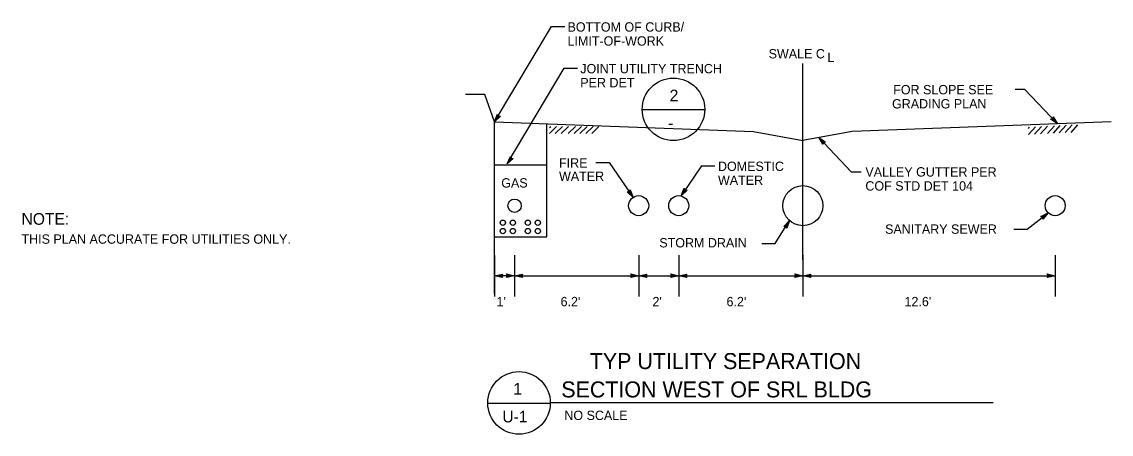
# Model space of a CAD drawing. Extents: x -1680 to 1155, y -802 to 799.
# Drawn here: x -1680 to -864, y 490 to 799 of the extents above; entities that cross this region are included whole.
import ezdxf

# ---------------------------------------------------------------- set-up
doc = ezdxf.new("R2010")
doc.units = 0
for name, color, linetype in [('New Utility (40)', 7, 'Continuous'), ('Nongeo Data(60)', 7, 'Continuous'), ('Sheet Format(10)', 7, 'Continuous')]:
    doc.layers.add(name, color=color, linetype=linetype)

msp = doc.modelspace()

# ---------------------------------------------------------------- linework, layer by layer
at = {"layer": 'Nongeo Data(60)'}
for p, q in [((-1325.56, 723.99), (-1282.86, 795.41)), ((-1282.86, 795.41), (-1272.86, 795.41)), ((-1094.56, 620.62), (-1094.56, 767.64)), ((-1315.99, 692.36), (-1273.29, 764.2)), ((-1273.29, 764.2), (-1263.29, 764.2)), ((-1332.86, 744.3), (-1347.41, 744.3)), ((-1325.56, 723.99), (-1332.86, 744.3)), ((-928.19, 748.17), (-935.6, 748.17)), ((-903.83, 722.45), (-928.19, 748.17)), ((-1325.56, 723.99), (-1323.24, 729.68)), ((-1321.05, 728.17), (-1325.56, 723.99)), ((-1324.77, 725.14), (-1323.08, 729.29)), ((-1321.46, 728.19), (-1324.77, 725.13)), ((-1323.99, 726.26), (-1322.9, 728.94)), ((-1321.89, 728.2), (-1323.99, 726.26)), ((-1323.24, 729.68), (-1323.24, 729.68)), ((-1323.24, 729.68), (-1322.6, 728.27)), ((-1323.2, 727.4), (-1322.73, 728.55)), ((-1322.28, 728.26), (-1323.2, 727.4)), ((-1322.6, 728.27), (-1321.05, 728.17)), ((-1321.05, 728.17), (-1321.05, 728.17)), ((-1215.19, 733.21), (-1168.07, 733.21)), ((-907.41, 726.22), (-906.99, 727.73)), ((-907.33, 726.54), (-906.68, 725.46)), ((-907.19, 726.91), (-905.73, 724.46)), ((-907.09, 727.32), (-904.78, 723.45)), ((-906.99, 727.73), (-906.99, 727.73)), ((-906.99, 727.73), (-903.83, 722.45)), ((-1325.56, 723.99), (-1131.48, 716.55)), ((-1325.56, 723.99), (-1325.56, 723.99)), ((-1325.56, 595.29), (-1325.56, 723.99)), ((-1286.35, 637.8), (-1286.35, 722.49)), ((-1284.49, 715.06), (-1279.02, 720.53)), ((-1284.41, 719.56), (-1283.44, 720.53)), ((-1280.07, 715.06), (-1274.6, 720.53)), ((-1275.65, 715.06), (-1270.18, 720.53)), ((-1270.37, 715.06), (-1264.9, 720.53)), ((-1265.95, 715.06), (-1260.48, 720.53)), ((-1261.53, 715.06), (-1256.06, 720.53)), ((-1257.11, 715.06), (-1251.64, 720.53)), ((-1252.69, 715.06), (-1247.39, 720.36)), ((-863.56, 723.99), (-1057.64, 716.55)), ((-925.57, 718.97), (-924.65, 719.99)), ((-925.43, 714.47), (-920.23, 720.2)), ((-921.01, 714.69), (-915.82, 720.42)), ((-916.6, 714.91), (-911.41, 720.64)), ((-911.32, 715.16), (-906.13, 720.89)), ((-908.92, 725.89), (-907.41, 726.22)), ((-903.83, 722.45), (-908.92, 725.89)), ((-908.92, 725.89), (-908.92, 725.89)), ((-904.79, 723.46), (-908.5, 725.97)), ((-905.73, 724.46), (-908.13, 726.08)), ((-906.68, 725.46), (-907.71, 726.15)), ((-906.91, 715.38), (-901.71, 721.11)), ((-903.83, 722.45), (-903.83, 722.45)), ((-902.49, 715.6), (-897.3, 721.33)), ((-898.08, 715.81), (-892.89, 721.54)), ((-893.67, 716.03), (-888.63, 721.59)), ((-1131.48, 716.55), (-1094.56, 709.98)), ((-1057.64, 716.55), (-1094.56, 709.98)), ((-1082.66, 712.1), (-1058.31, 686.38)), ((-1079.51, 706.82), (-1082.66, 712.1)), ((-1082.66, 712.1), (-1082.66, 712.1)), ((-1082.66, 712.1), (-1077.57, 708.65)), ((-1079.4, 707.22), (-1081.72, 711.09)), ((-1081.71, 711.09), (-1078, 708.58)), ((-1079.3, 707.64), (-1080.77, 710.09)), ((-1080.77, 710.09), (-1078.37, 708.47)), ((-1079.17, 708), (-1079.82, 709.08)), ((-1079.82, 709.08), (-1078.79, 708.39)), ((-1079.09, 708.32), (-1079.51, 706.82)), ((-1079.51, 706.82), (-1079.51, 706.82)), ((-1077.57, 708.65), (-1079.09, 708.32)), ((-1077.57, 708.65), (-1077.57, 708.65)), ((-1315.99, 692.36), (-1313.67, 698.06)), ((-1311.48, 696.54), (-1315.99, 692.36)), ((-1315.2, 693.51), (-1313.51, 697.66)), ((-1311.89, 696.56), (-1315.2, 693.5)), ((-1314.42, 694.63), (-1313.33, 697.31)), ((-1312.32, 696.57), (-1314.42, 694.63)), ((-1313.67, 698.06), (-1313.67, 698.06)), ((-1313.67, 698.06), (-1313.03, 696.64)), ((-1313.63, 695.77), (-1313.16, 696.92)), ((-1312.71, 696.63), (-1313.63, 695.77)), ((-1313.03, 696.64), (-1311.48, 696.54)), ((-1311.48, 696.54), (-1311.48, 696.54)), ((-1286.35, 691.49), (-1325.56, 691.49)), ((-1315.99, 692.36), (-1315.99, 692.36)), ((-1249.65, 693.39), (-1239.65, 693.39)), ((-1239.65, 693.39), (-1221.77, 667.31)), ((-1170.61, 690.87), (-1185.78, 668.39)), ((-1170.61, 690.87), (-1160.61, 690.87)), ((-1058.31, 686.38), (-1050.9, 686.38)), ((-1226.26, 671.5), (-1224.71, 671.6)), ((-1221.77, 667.31), (-1226.26, 671.5)), ((-1226.26, 671.5), (-1226.26, 671.5)), ((-1222.56, 668.45), (-1225.83, 671.51)), ((-1223.33, 669.59), (-1225.45, 671.56)), ((-1224.11, 670.73), (-1225.02, 671.57)), ((-1224.71, 671.6), (-1224.06, 673.01)), ((-1224.58, 671.9), (-1224.11, 670.73)), ((-1224.39, 672.24), (-1223.33, 669.59)), ((-1224.23, 672.63), (-1222.55, 668.44)), ((-1224.06, 673.01), (-1224.06, 673.01)), ((-1224.06, 673.01), (-1221.77, 667.31)), ((-1185.78, 668.39), (-1183.52, 674.1)), ((-1181.31, 672.61), (-1185.78, 668.39)), ((-1185, 669.54), (-1183.36, 673.71)), ((-1181.72, 672.63), (-1185, 669.53)), ((-1184.23, 670.68), (-1183.17, 673.37)), ((-1182.15, 672.64), (-1184.23, 670.68)), ((-1183.52, 674.1), (-1183.52, 674.1)), ((-1183.52, 674.1), (-1182.87, 672.7)), ((-1183.45, 671.82), (-1183, 672.97)), ((-1182.54, 672.69), (-1183.45, 671.82)), ((-1182.87, 672.7), (-1181.31, 672.61)), ((-1181.31, 672.61), (-1181.31, 672.61)), ((-1221.77, 667.31), (-1221.77, 667.31)), ((-1185.78, 668.39), (-1185.78, 668.39)), ((-926.54, 643.41), (-910.83, 655.76)), ((-916.37, 653.11), (-910.83, 655.76)), ((-914.92, 652.55), (-916.37, 653.11)), ((-916.37, 653.11), (-916.37, 653.11)), ((-915.98, 652.97), (-911.91, 654.91)), ((-915.58, 652.83), (-913, 654.06)), ((-915.22, 652.66), (-914.09, 653.21)), ((-914.09, 653.21), (-914.87, 652.25)), ((-913, 654.06), (-914.83, 651.82)), ((-911.92, 654.9), (-914.76, 651.44)), ((-910.83, 655.76), (-914.72, 651.01)), ((-910.83, 655.76), (-910.83, 655.76)), ((-1115.35, 632.79), (-1104.62, 649.98)), ((-1108.93, 645.6), (-1104.62, 649.98)), ((-1107.37, 645.57), (-1108.93, 645.6)), ((-1108.93, 645.6), (-1108.93, 645.6)), ((-1108.52, 645.59), (-1105.35, 648.81)), ((-1108.09, 645.6), (-1106.08, 647.63)), ((-1107.7, 645.57), (-1106.82, 646.46)), ((-1106.67, 644.18), (-1107.37, 645.57)), ((-1106.82, 646.46), (-1107.23, 645.3)), ((-1106.08, 647.63), (-1107.05, 644.91)), ((-1105.35, 648.79), (-1106.85, 644.57)), ((-1104.62, 649.98), (-1106.67, 644.18)), ((-1104.62, 649.98), (-1104.62, 649.98)), ((-914.72, 651.01), (-914.92, 652.55)), ((-914.72, 651.01), (-914.72, 651.01)), ((-1325.56, 637.8), (-1286.35, 637.8)), ((-1106.67, 644.18), (-1106.67, 644.18)), ((-936.54, 643.41), (-926.54, 643.41)), ((-1125.35, 632.79), (-1115.35, 632.79)), ((-1325.56, 624.01), (-1325.56, 593.15)), ((-1310.56, 624.01), (-1310.56, 593.15)), ((-1217.56, 624.01), (-1217.56, 593.15)), ((-1187.56, 624.01), (-1187.56, 593.15)), ((-1094.56, 624.01), (-1094.56, 593.15)), ((-905.56, 624.01), (-905.56, 593.15)), ((-1325.56, 608.58), (-1319.56, 609.91)), ((-1310.56, 608.58), (-1325.56, 608.58)), ((-1319.56, 607.24), (-1325.56, 608.58)), ((-1325.56, 608.58), (-1325.56, 608.58)), ((-1319.77, 607.6), (-1324.18, 608.58)), ((-1324.17, 608.58), (-1319.79, 609.55)), ((-1322.79, 608.58), (-1319.97, 609.2)), ((-1320.01, 607.96), (-1322.79, 608.58)), ((-1321.41, 608.58), (-1320.2, 608.85)), ((-1320.18, 608.3), (-1321.41, 608.58)), ((-1319.56, 609.91), (-1320.36, 608.58)), ((-1320.36, 608.58), (-1319.56, 607.24)), ((-1319.56, 609.91), (-1319.56, 609.91)), ((-1319.56, 607.24), (-1319.56, 607.24)), ((-1315.76, 608.58), (-1316.56, 609.92)), ((-1316.56, 609.92), (-1316.56, 609.92)), ((-1316.56, 609.92), (-1310.56, 608.58)), ((-1310.56, 608.58), (-1316.56, 607.25)), ((-1316.56, 607.25), (-1315.76, 608.58)), ((-1316.56, 607.25), (-1316.56, 607.25)), ((-1316.34, 609.56), (-1311.94, 608.58)), ((-1311.95, 608.58), (-1316.32, 607.61)), ((-1313.32, 608.58), (-1316.15, 607.96)), ((-1316.11, 609.2), (-1313.32, 608.58)), ((-1315.93, 608.86), (-1314.7, 608.58)), ((-1314.7, 608.58), (-1315.91, 608.32)), ((-1310.56, 608.58), (-1304.56, 609.91)), ((-1310.56, 608.58), (-1217.56, 608.58)), ((-1310.56, 608.58), (-1310.56, 608.58)), ((-1304.56, 607.24), (-1310.56, 608.58)), ((-1310.56, 608.58), (-1310.56, 608.58)), ((-1304.77, 607.6), (-1309.18, 608.58)), ((-1309.17, 608.58), (-1304.79, 609.55)), ((-1307.79, 608.58), (-1304.97, 609.2)), ((-1305.01, 607.96), (-1307.79, 608.58)), ((-1306.41, 608.58), (-1305.2, 608.85)), ((-1305.18, 608.3), (-1306.41, 608.58)), ((-1304.56, 609.91), (-1305.36, 608.58)), ((-1305.36, 608.58), (-1304.56, 607.24)), ((-1304.56, 609.91), (-1304.56, 609.91)), ((-1304.56, 607.24), (-1304.56, 607.24)), ((-1222.76, 608.58), (-1223.56, 609.92)), ((-1223.56, 609.92), (-1223.56, 609.92)), ((-1223.56, 609.92), (-1217.56, 608.58)), ((-1217.56, 608.58), (-1223.56, 607.25)), ((-1223.56, 607.25), (-1222.76, 608.58)), ((-1223.56, 607.25), (-1223.56, 607.25)), ((-1223.34, 609.56), (-1218.94, 608.58)), ((-1218.95, 608.58), (-1223.32, 607.61)), ((-1220.32, 608.58), (-1223.15, 607.96)), ((-1223.11, 609.2), (-1220.32, 608.58)), ((-1222.93, 608.86), (-1221.7, 608.58)), ((-1221.7, 608.58), (-1222.91, 608.32)), ((-1217.56, 608.58), (-1211.56, 609.91)), ((-1217.56, 608.58), (-1187.56, 608.58)), ((-1217.56, 608.58), (-1217.56, 608.58)), ((-1211.56, 607.24), (-1217.56, 608.58)), ((-1217.56, 608.58), (-1217.56, 608.58)), ((-1211.77, 607.6), (-1216.18, 608.58)), ((-1216.17, 608.58), (-1211.79, 609.55)), ((-1214.79, 608.58), (-1211.97, 609.2)), ((-1212.01, 607.96), (-1214.79, 608.58)), ((-1213.41, 608.58), (-1212.2, 608.85)), ((-1212.18, 608.3), (-1213.41, 608.58)), ((-1211.56, 609.91), (-1212.36, 608.58)), ((-1212.36, 608.58), (-1211.56, 607.24)), ((-1211.56, 609.91), (-1211.56, 609.91)), ((-1211.56, 607.24), (-1211.56, 607.24)), ((-1192.76, 608.58), (-1193.56, 609.92)), ((-1193.56, 609.92), (-1193.56, 609.92)), ((-1193.56, 609.92), (-1187.56, 608.58)), ((-1187.56, 608.58), (-1193.56, 607.25)), ((-1193.56, 607.25), (-1192.76, 608.58)), ((-1193.56, 607.25), (-1193.56, 607.25)), ((-1193.34, 609.56), (-1188.94, 608.58)), ((-1188.95, 608.58), (-1193.32, 607.61)), ((-1190.32, 608.58), (-1193.15, 607.96)), ((-1193.11, 609.2), (-1190.32, 608.58)), ((-1192.93, 608.86), (-1191.7, 608.58)), ((-1191.7, 608.58), (-1192.91, 608.32)), ((-1187.56, 608.58), (-1181.56, 609.91)), ((-1187.56, 608.58), (-1094.56, 608.58)), ((-1187.56, 608.58), (-1187.56, 608.58)), ((-1181.56, 607.24), (-1187.56, 608.58)), ((-1187.56, 608.58), (-1187.56, 608.58)), ((-1181.77, 607.6), (-1186.18, 608.58)), ((-1186.17, 608.58), (-1181.79, 609.55)), ((-1184.79, 608.58), (-1181.97, 609.2)), ((-1182.01, 607.96), (-1184.79, 608.58)), ((-1183.41, 608.58), (-1182.2, 608.85)), ((-1182.18, 608.3), (-1183.41, 608.58)), ((-1181.56, 609.91), (-1182.36, 608.58)), ((-1182.36, 608.58), (-1181.56, 607.24)), ((-1181.56, 609.91), (-1181.56, 609.91)), ((-1181.56, 607.24), (-1181.56, 607.24)), ((-1099.76, 608.58), (-1100.56, 609.92)), ((-1100.56, 609.92), (-1100.56, 609.92)), ((-1100.56, 609.92), (-1094.56, 608.58)), ((-1099.76, 608.58), (-1100.56, 609.92)), ((-1100.56, 609.92), (-1100.56, 609.92)), ((-1100.56, 609.92), (-1094.56, 608.58)), ((-1094.56, 608.58), (-1100.56, 607.25)), ((-1100.56, 607.25), (-1099.76, 608.58)), ((-1094.56, 608.58), (-1100.56, 607.25)), ((-1100.56, 607.25), (-1099.76, 608.58)), ((-1100.56, 607.25), (-1100.56, 607.25)), ((-1100.56, 607.25), (-1100.56, 607.25)), ((-1100.34, 609.56), (-1095.94, 608.58)), ((-1100.34, 609.56), (-1095.94, 608.58)), ((-1095.95, 608.58), (-1100.32, 607.61)), ((-1095.95, 608.58), (-1100.32, 607.61)), ((-1097.32, 608.58), (-1100.15, 607.96)), ((-1097.32, 608.58), (-1100.15, 607.96)), ((-1100.11, 609.2), (-1097.32, 608.58)), ((-1100.11, 609.2), (-1097.32, 608.58)), ((-1099.93, 608.86), (-1098.7, 608.58)), ((-1099.93, 608.86), (-1098.7, 608.58)), ((-1098.7, 608.58), (-1099.91, 608.32)), ((-1098.7, 608.58), (-1099.91, 608.32)), ((-1094.56, 608.58), (-1088.56, 609.91)), ((-1094.56, 608.58), (-905.56, 608.58)), ((-1094.56, 608.58), (-1094.56, 608.58)), ((-1094.56, 608.58), (-1094.56, 608.58)), ((-1088.56, 607.24), (-1094.56, 608.58)), ((-1094.56, 608.58), (-1094.56, 608.58)), ((-1088.77, 607.6), (-1093.18, 608.58)), ((-1093.17, 608.58), (-1088.79, 609.55)), ((-1091.79, 608.58), (-1088.97, 609.2)), ((-1089.01, 607.96), (-1091.79, 608.58)), ((-1090.41, 608.58), (-1089.2, 608.85)), ((-1089.18, 608.3), (-1090.41, 608.58)), ((-1088.56, 609.91), (-1089.36, 608.58)), ((-1089.36, 608.58), (-1088.56, 607.24)), ((-1088.56, 609.91), (-1088.56, 609.91)), ((-1088.56, 607.24), (-1088.56, 607.24)), ((-910.76, 608.58), (-911.56, 609.92)), ((-911.56, 609.92), (-911.56, 609.92)), ((-911.56, 609.92), (-905.56, 608.58)), ((-905.56, 608.58), (-911.56, 607.25)), ((-911.56, 607.25), (-910.76, 608.58)), ((-911.56, 607.25), (-911.56, 607.25)), ((-911.34, 609.56), (-906.94, 608.58)), ((-906.95, 608.58), (-911.32, 607.61)), ((-908.32, 608.58), (-911.15, 607.96)), ((-911.11, 609.2), (-908.32, 608.58)), ((-910.93, 608.86), (-909.7, 608.58)), ((-909.7, 608.58), (-910.91, 608.32)), ((-905.56, 608.58), (-905.56, 608.58)), ((-1330.88, 513.27), (-1283.76, 513.27)), ((-952.1, 513.33), (-1283.76, 513.33))]:
    msp.add_line(p, q, dxfattribs=at)
for centre, radius in [((-1191.5, 733.27), 23.44), ((-1094.56, 661.1), 15), ((-1310.56, 661.1), 5), ((-1217.56, 661.1), 7.5), ((-1187.56, 661.1), 7.5), ((-905.56, 661.1), 7.5), ((-1319.33, 648.31), 2), ((-1311.84, 648.31), 2), ((-1300.6, 648.31), 2), ((-1293.12, 648.31), 2), ((-1319.33, 642.06), 2), ((-1311.84, 642.06), 2), ((-1300.6, 642.06), 2), ((-1293.12, 642.06), 2), ((-1307.2, 513.33), 23.44)]:
    msp.add_circle(centre, radius, dxfattribs=at)

# ---------------------------------------------------------------- texts
at = {"layer": 'New Utility (40)'}
for s, height, p in [('NOTE:', 8.75, (-1679.92, 646.81)), ('THIS PLAN ACCURATE FOR UTILITIES ONLY.', 7, (-1679.92, 632.58))]:
    msp.add_text(s, height=height, dxfattribs=at).set_placement(p)
at = {"layer": 'Nongeo Data(60)'}
for s, height, p in [('BOTTOM OF CURB/', 7, (-1270.86, 791.49)), ('LIMIT-OF-WORK', 7, (-1270.86, 780.99)), ('SWALE C', 7, (-1120.2, 771.41)), ('L', 7, (-1076.23, 768.71)), ('JOINT UTILITY TRENCH', 7, (-1261.29, 760.27)), ('PER DET', 7, (-1261.29, 749.77)), ('FOR SLOPE SEE', 7, (-1026.86, 744.51)), ('2', 8.75, (-1194.37, 739.25)), ('GRADING PLAN', 7, (-1027.76, 733.94)), ('-', 8.75, (-1195.49, 718.69)), ('FIRE', 7, (-1277.23, 689.63)), ('DOMESTIC', 7, (-1158.14, 687.11)), ('WATER', 7, (-1277.23, 679.64)), ('VALLEY GUTTER PER', 7, (-1047.72, 682.91)), ('GAS', 7, (-1320.5, 674.67)), ('WATER', 7, (-1158.14, 676.7)), ('COF STD DET 104', 7, (-1047.72, 672.41)), ('SANITARY SEWER', 7, (-1032.96, 640.05)), ('STORM DRAIN', 7, (-1202.1, 629.82)), ("1'", 7, (-1324.04, 585.75)), ("6.2'", 7, (-1276.05, 585.75)), ("2'", 7, (-1207.21, 585.75)), ("6.2'", 7, (-1151.75, 585.75)), ("12.6'", 7, (-1018.41, 585.75)), ('TYP UTILITY SEPARATION', 12, (-1254.19, 538.68)), ('1', 8.75, (-1311.51, 519.47)), ('SECTION WEST OF SRL BLDG', 12, (-1275.54, 517.44)), ('U-1', 8.75, (-1319.67, 498.75))]:
    msp.add_text(s, height=height, dxfattribs=at).set_placement(p)
at = {"layer": 'Sheet Format(10)'}
msp.add_text('NO SCALE', height=7, dxfattribs=at).set_placement((-1273.23, 500.53))

doc.saveas('drawing.dxf')
